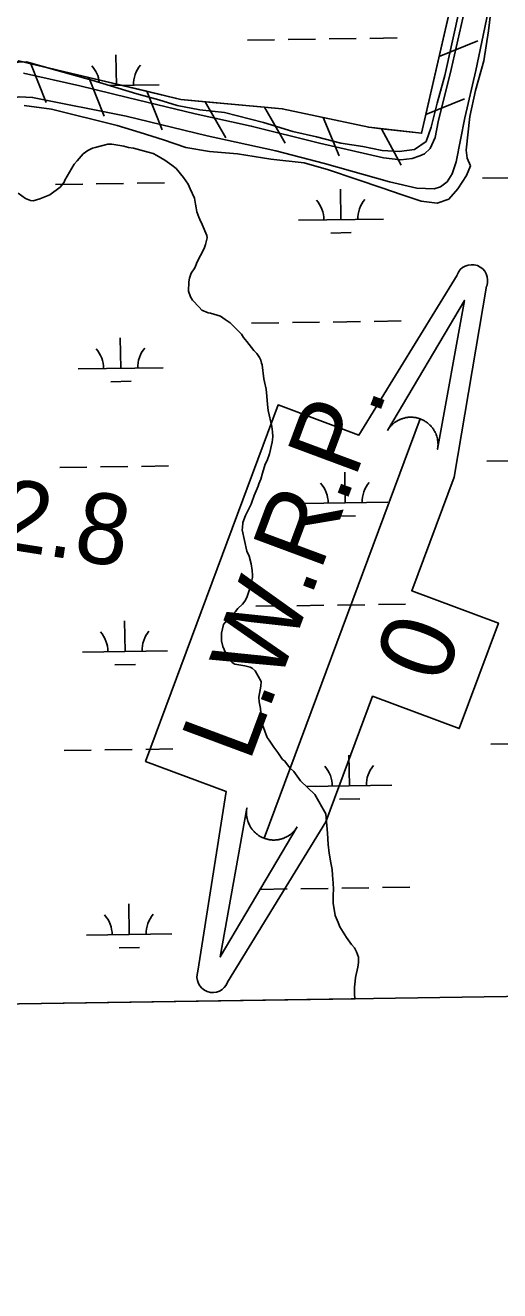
# Model space of a CAD drawing. Extents: x 3807117 to 3845308, y 337856 to 363736.
# Drawn here: x 3833871 to 3834429, y 343281 to 344768 of the extents above; entities that cross this region are included whole.
import ezdxf

# ---------------------------------------------------------------- set-up
doc = ezdxf.new("R2010")
doc.units = 0
for name, color, linetype in [('V-GRID-FRAM', 7, 'Continuous'), ('V-LEVE-TOET', 7, 'Continuous'), ('V-RIVR-EDGE', 7, 'Continuous'), ('V-RIVR-RANG-IDEN', 7, 'Continuous'), ('V-RRAP-FSHR', 7, 'Continuous'), ('V-SITE-VEGE', 7, 'Continuous'), ('V-TOPO-WATR-IDEN', 7, 'Continuous'), ('V-WETL-SWMP', 7, 'Continuous')]:
    doc.layers.add(name, color=color, linetype=linetype)

msp = doc.modelspace()

# ---------------------------------------------------------------- linework, layer by layer
at = {"layer": 'V-GRID-FRAM'}
msp.add_lwpolyline([(3811100.6, 361461.9), (3842914.2, 361938.5), (3843194.5, 343758.3), (3811365, 343281.4), (3811100.6, 361461.9)], dxfattribs=at)
at = {"layer": 'V-LEVE-TOET'}
for points in [[(3834420.2, 344809.1), (3834400.7, 344715.2), (3834387.8, 344659.5), (3834377.7, 344607.9), (3834373, 344593.7), (3834366.9, 344584.3), (3834359.3, 344578.4), (3834351.6, 344576.4), (3834331.4, 344577.1), (3834299.1, 344584.5), (3834222.9, 344605.8), (3834165.5, 344620.9), (3834084.7, 344638.6), (3833989.5, 344661.7), (3833879.6, 344683.7), (3833863.7, 344684.5), (3833851.9, 344682.1), (3833845.7, 344680.3), (3833834.3, 344673.2), (3833816.6, 344660.1), (3833785.8, 344626), (3833737, 344568.4)], [(3833869, 344712), (3833935.2, 344697.4), (3833991.3, 344683.7), (3834070.7, 344664.4), (3834136.7, 344649.9), (3834217.1, 344629.8), (3834292.2, 344612.8), (3834312.7, 344610.1), (3834325.8, 344611.9), (3834334.7, 344614.9), (3834340.3, 344617.4), (3834347, 344623.5), (3834352.7, 344636.7), (3834356.4, 344654.8), (3834371.8, 344716.3), (3834391.2, 344803)]]:
    msp.add_lwpolyline(points, dxfattribs=at)
at = {"layer": 'V-RIVR-EDGE'}
msp.add_spline([(3833993.6, 346073.1), (3834014.8, 346049.1), (3834027.9, 346045), (3834044.2, 346044.5), (3834056.4, 346046.8), (3834063.2, 346046.7), (3834065.5, 346045.4), (3834066.8, 346025), (3834070.8, 346004.7), (3834083.3, 345964.4), (3834083.8, 345960.8), (3834080.2, 345959.9), (3834071.6, 345964), (3834066.6, 345963.1), (3834057.1, 345958.1), (3834056.2, 345945.9), (3834053.9, 345939.6), (3834045.3, 345936), (3834032.2, 345933.8), (3834020.9, 345934.3), (3834010.5, 345930.7), (3833991.4, 345919.4), (3833968.3, 345903.6), (3833937.1, 345880.2), (3833918, 345855.8), (3833899.9, 345825.6), (3833887.6, 345788.5), (3833879.4, 345756.5), (3833874.3, 345710.4), (3833869.2, 345675.1), (3833852.3, 345618.6), (3833845.5, 345588.3), (3833842.7, 345557.2), (3833837.6, 345515.1), (3833834.3, 345463.1), (3833833.3, 345422.9), (3833835.5, 345389.9), (3833826.7, 345327.5), (3833812.6, 345266), (3833811.6, 345236.2), (3833805.6, 345198.2), (3833800.1, 345162.1), (3833798.7, 345131.8), (3833801.8, 345114.6), (3833810.8, 345092.4), (3833826.6, 345068.4), (3833838.7, 345048.9), (3833853.2, 345041.2), (3833864.5, 345032.1), (3833872.1, 345019.5), (3833872.1, 345008.2), (3833866.1, 344947.6), (3833859.1, 344872.5), (3833858.2, 344868), (3833853.6, 344868), (3833833.3, 344878), (3833815.7, 344894.8), (3833804.9, 344906.1), (3833797.7, 344908.9), (3833783.2, 344908.5), (3833736.6, 344893.2), (3833706.2, 344865.7), (3833687.6, 344845.4), (3833676.3, 344827.3), (3833665.4, 344800.7), (3833650.8, 344767.7), (3833632.6, 344715.8), (3833615.3, 344663.8), (3833598.9, 344623.1), (3833579.4, 344582.5), (3833566.6, 344539.6), (3833556.6, 344505.7), (3833525.6, 344416.7), (3833510.6, 344373.8), (3833496, 344333.1), (3833486.9, 344308.7), (3833473.3, 344271.2), (3833455.1, 344226.1), (3833441.8, 344180.9), (3833432.7, 344150.1), (3833396.3, 344055.7), (3833377.2, 344001.1), (3833358.1, 343958.6), (3833345.4, 343934.2), (3833328.1, 343879.6), (3833313, 343821.7), (3833296.6, 343775.6), (3833286.1, 343739.5), (3833276, 343687.1), (3833267.4, 343655), (3833255.1, 343614.3), (3833253.2, 343609.3)], degree=3, dxfattribs=at)
at = {"layer": 'V-RRAP-FSHR'}
for p, q in [((3834357.6, 344731.7), (3834402.9, 344750.1)), ((3833877.6, 344723.2), (3833895.6, 344677.8)), ((3833945.7, 344707), (3833963.7, 344661.6)), ((3834013.8, 344690.8), (3834031.8, 344645.4)), ((3834342, 344663.5), (3834387.2, 344681.9)), ((3834082.6, 344678.6), (3834106.8, 344636.3)), ((3834152.3, 344672.3), (3834176.5, 344629.9)), ((3834221.1, 344660.1), (3834240.1, 344615.1)), ((3834289.8, 344646.9), (3834313.1, 344603.9))]:
    msp.add_line(p, q, dxfattribs=at)
for points in [[(3833587.4, 344306.4), (3833655.4, 344519.2), (3833727.5, 344609.7), (3833863.6, 344726.6), (3834054, 344681.3), (3834173.1, 344670.3), (3834274.8, 344648.6), (3834336.9, 344641.5), (3834420.3, 345004.8), (3834419, 345047), (3834294.5, 345071.8), (3834199.7, 345056.1), (3834130, 345085.7), (3834142, 345154.9), (3834217.5, 345146.3), (3834217.8, 345245.8), (3834184, 345393.3)], [(3834357.6, 344731.7), (3834373.3, 344800)], [(3833821.4, 344690.4), (3833863.6, 344726.6), (3833877.6, 344723.2)], [(3834342, 344663.5), (3834357.6, 344731.7)], [(3833877.6, 344723.2), (3833945.7, 344707)], [(3833945.7, 344707), (3834013.8, 344690.8)], [(3834013.8, 344690.8), (3834054, 344681.3), (3834082.6, 344678.6)], [(3834082.6, 344678.6), (3834152.3, 344672.3)], [(3834152.3, 344672.3), (3834173.1, 344670.3), (3834221.1, 344660.1)], [(3834221.1, 344660.1), (3834274.8, 344648.6), (3834289.8, 344646.9)], [(3834289.8, 344646.9), (3834336.9, 344641.5), (3834342, 344663.5)]]:
    msp.add_lwpolyline(points, dxfattribs=at)
at = {"layer": 'V-SITE-VEGE'}
for p, q in [((3833939.1, 344617.4), (3833944.6, 344621.1)), ((3833944.6, 344621.1), (3833950.1, 344623.9)), ((3833950.1, 344623.9), (3833953.4, 344624.8)), ((3833953.4, 344624.8), (3833968.1, 344628.6)), ((3833968.1, 344628.6), (3833972.7, 344628.6)), ((3833972.7, 344628.6), (3833987, 344626.3)), ((3833987, 344626.3), (3833992.5, 344624.9)), ((3833992.5, 344624.9), (3833998.1, 344624)), ((3833998.1, 344624), (3834015.6, 344619.4)), ((3833928.5, 344605), (3833932.2, 344609.1)), ((3833932.2, 344609.1), (3833939.1, 344617.4)), ((3834015.6, 344619.4), (3834021.6, 344617.6)), ((3834021.6, 344617.6), (3834025.7, 344615.3)), ((3834025.7, 344615.3), (3834035, 344609.8)), ((3834035, 344609.8), (3834043.3, 344604.2)), ((3833917.5, 344586.5), (3833928.5, 344605)), ((3834043.3, 344604.2), (3834048.3, 344600.1)), ((3834048.3, 344600.1), (3834057.1, 344589.5)), ((3833900, 344569), (3833912, 344578.2)), ((3833912, 344578.2), (3833916.6, 344584.2)), ((3833916.6, 344584.2), (3833917.5, 344586.5)), ((3834057.1, 344589.5), (3834062.7, 344581.7)), ((3834062.7, 344581.7), (3834065, 344576.2)), ((3834065, 344576.2), (3834070.1, 344565.1)), ((3833862.6, 344571.2), (3833871.4, 344564.8)), ((3833871.4, 344564.8), (3833877.4, 344562.5)), ((3833877.4, 344562.5), (3833880.2, 344562)), ((3833880.2, 344562), (3833888, 344564.4)), ((3833888, 344564.4), (3833900, 344569)), ((3834070.1, 344565.1), (3834071, 344558.2)), ((3834071, 344558.2), (3834071.9, 344554)), ((3834071.9, 344554), (3834072.9, 344549)), ((3834072.9, 344549), (3834075.2, 344543)), ((3834075.2, 344543), (3834076.1, 344540.2)), ((3834076.1, 344540.2), (3834078.9, 344534.2)), ((3834078.9, 344534.2), (3834084.4, 344521.3)), ((3834084.9, 344518.6), (3834083.1, 344510.7)), ((3834084.4, 344521.3), (3834084.9, 344518.6)), ((3834081.2, 344506.1), (3834072.9, 344489.5)), ((3834083.1, 344510.7), (3834081.2, 344506.1)), ((3834072, 344487.2), (3834070.2, 344483.5)), ((3834072.9, 344489.5), (3834072, 344487.2)), ((3834066.1, 344477.1), (3834064.2, 344471.1)), ((3834070.2, 344483.5), (3834066.1, 344477.1)), ((3834063.3, 344466.9), (3834062.9, 344455.9)), ((3834064.2, 344471.1), (3834063.3, 344466.9)), ((3834062.9, 344455.9), (3834065.2, 344449.4)), ((3834065.2, 344449.4), (3834067.5, 344445.3)), ((3834067.5, 344445.3), (3834075.3, 344437)), ((3834075.3, 344437), (3834078.6, 344433.8)), ((3834078.6, 344433.8), (3834085.9, 344430.5)), ((3834085.9, 344430.5), (3834088.7, 344430.1)), ((3834088.7, 344430.1), (3834100.7, 344426.4)), ((3834100.7, 344426.4), (3834106.2, 344422.7)), ((3834106.2, 344422.7), (3834111.8, 344418.6)), ((3834111.8, 344418.6), (3834125.2, 344405.3)), ((3834125.2, 344405.3), (3834126.5, 344403.4)), ((3834126.5, 344403.4), (3834127.5, 344401.6)), ((3834127.5, 344401.6), (3834131.6, 344397)), ((3834131.6, 344397), (3834139.9, 344386.4)), ((3834139.9, 344386.4), (3834143.2, 344382.7)), ((3834143.2, 344382.7), (3834146.4, 344378.1)), ((3834146.4, 344378.1), (3834147.8, 344374.9)), ((3834147.8, 344374.9), (3834148.7, 344371.2)), ((3834148.7, 344371.2), (3834149.6, 344369.3)), ((3834149.6, 344369.3), (3834151.5, 344352.8)), ((3834151.5, 344352.8), (3834152.4, 344349.5)), ((3834152.4, 344349.5), (3834154.3, 344340.8)), ((3834154.3, 344340.8), (3834155.2, 344332.5)), ((3834155.2, 344332.5), (3834155.7, 344322.8)), ((3834155.7, 344322.8), (3834156.6, 344315.9)), ((3834156.6, 344315.9), (3834160.8, 344297)), ((3834160.8, 344297), (3834161.7, 344290.5)), ((3834161.3, 344278.6), (3834158.1, 344264.7)), ((3834162.2, 344284.6), (3834161.3, 344278.6)), ((3834161.7, 344290.5), (3834162.2, 344284.6)), ((3834158.1, 344264.7), (3834155.3, 344256.9)), ((3834153, 344252.7), (3834149.8, 344242.1)), ((3834155.3, 344256.9), (3834153, 344252.7)), ((3834148, 344235.2), (3834145.7, 344229.7)), ((3834149.8, 344242.1), (3834148, 344235.2)), ((3834144.8, 344226.9), (3834140.2, 344215.8)), ((3834145.7, 344229.7), (3834144.8, 344226.9)), ((3834136.5, 344205.7), (3834130.1, 344192.3)), ((3834137.4, 344208), (3834136.5, 344205.7)), ((3834140.2, 344215.8), (3834137.4, 344208)), ((3834130.1, 344192.3), (3834126.9, 344184)), ((3834126.4, 344178), (3834126, 344175.3)), ((3834126, 344175.3), (3834131.5, 344150.4)), ((3834126.9, 344184), (3834126.4, 344178)), ((3834131.5, 344150.4), (3834134.3, 344144.4)), ((3834134.3, 344144.4), (3834136.6, 344135.6)), ((3834136.6, 344135.6), (3834137.6, 344127.8)), ((3834138, 344119.5), (3834134.8, 344105.2)), ((3834137.6, 344127.8), (3834138, 344122.3)), ((3834138, 344122.3), (3834138, 344119.5)), ((3834133, 344100.6), (3834131.6, 344096)), ((3834134.8, 344105.2), (3834133, 344100.6)), ((3834126.6, 344088.2), (3834121, 344083.1)), ((3834129.3, 344091.8), (3834126.6, 344088.2)), ((3834131.6, 344096), (3834129.3, 344091.8)), ((3834110.9, 344072), (3834105.4, 344066)), ((3834118.3, 344079.4), (3834110.9, 344072)), ((3834121, 344083.1), (3834118.3, 344079.4)), ((3834104, 344064.1), (3834101.7, 344054)), ((3834105.4, 344066), (3834104, 344064.1)), ((3834101.7, 344054), (3834101.7, 344045.2)), ((3834101.7, 344045.2), (3834103.1, 344038.3)), ((3834103.1, 344038.3), (3834109.6, 344024.1)), ((3834109.6, 344024.1), (3834114.2, 344019.5)), ((3834114.2, 344019.5), (3834117.5, 344017.6)), ((3834117.5, 344017.6), (3834129, 344015.8)), ((3834129, 344015.8), (3834135.4, 344014)), ((3834135.4, 344014), (3834137.7, 344013)), ((3834137.7, 344013), (3834141.4, 344009.8)), ((3834141.4, 344009.8), (3834148.4, 343997.4)), ((3834148.4, 343997.4), (3834147.9, 343991.9)), ((3834147.9, 343991.9), (3834145.6, 343978.9)), ((3834145.6, 343978.9), (3834146.1, 343973.4)), ((3834146.1, 343973.4), (3834147.5, 343965.6)), ((3834147.5, 343965.6), (3834148.9, 343949.5)), ((3834148.9, 343949.5), (3834149.8, 343946.2)), ((3834149.8, 343946.2), (3834155.4, 343931.5)), ((3834155.4, 343931.5), (3834157.7, 343928.3)), ((3834157.7, 343928.3), (3834163.2, 343920)), ((3834163.2, 343920), (3834167.9, 343914)), ((3834167.9, 343914), (3834173.4, 343905.7)), ((3834173.4, 343905.7), (3834175.7, 343903.9)), ((3834175.7, 343903.9), (3834180.8, 343897.4)), ((3834180.8, 343897.4), (3834182.6, 343895.6)), ((3834182.6, 343895.6), (3834186.8, 343891.4)), ((3834186.8, 343891.4), (3834194.6, 343880.4)), ((3834194.6, 343880.4), (3834211.3, 343864.3)), ((3834211.3, 343864.3), (3834224.2, 343841.7)), ((3834224.2, 343841.7), (3834226.5, 343819.1)), ((3834226.5, 343819.1), (3834227, 343805.8)), ((3834227, 343805.8), (3834228.4, 343795.6)), ((3834228.4, 343795.6), (3834230.3, 343784.1)), ((3834230.3, 343784.1), (3834231.7, 343776.3)), ((3834231.7, 343776.3), (3834232.1, 343769.8)), ((3834232.1, 343769.8), (3834233.1, 343760.1)), ((3834233.1, 343760.1), (3834233.5, 343753.2)), ((3834233.5, 343753.2), (3834233.1, 343746.3)), ((3834233.1, 343746.3), (3834233.1, 343736.6)), ((3834233.1, 343736.6), (3834235.4, 343722.4)), ((3834235.4, 343722.4), (3834238.7, 343714.1)), ((3834238.7, 343714.1), (3834241, 343709)), ((3834241, 343709), (3834248.8, 343696.6)), ((3834248.8, 343696.6), (3834254.4, 343688.3)), ((3834254.4, 343688.3), (3834258.1, 343684.1)), ((3834258.1, 343684.1), (3834260.4, 343679.5)), ((3834260.4, 343679.5), (3834262.7, 343673.5)), ((3834262.7, 343673.5), (3834262.7, 343667.1)), ((3834261.8, 343661.6), (3834259.1, 343649.6)), ((3834262.7, 343667.1), (3834261.8, 343661.6)), ((3834258.6, 343641.3), (3834258.1, 343638.5)), ((3834259.1, 343649.6), (3834258.6, 343641.3)), ((3834258.8, 343624.4), (3833426.5, 343611.9)), ((3834258.1, 343638.5), (3834258.2, 343628.4)), ((3834258.2, 343628.4), (3834258.8, 343624.4))]:
    msp.add_line(p, q, dxfattribs=at)
at = {"layer": 'V-TOPO-WATR-IDEN'}
msp.add_line((3834152, 343813), (3834335.4, 344305.8), dxfattribs=at)
for points in [[(3834074.1, 343656.8), (3834107.4, 343868), (3834012.4, 343903.3), (3834168.3, 344322.2), (3834263.3, 344286.9), (3834378.6, 344474.9)], [(3834413.4, 344462), (3834375.1, 344237.3), (3834325.4, 344103.9), (3834427.3, 344066), (3834381.2, 343941.9), (3834279.3, 343979.9), (3834224.4, 343832.4), (3834108.9, 343643.8)]]:
    msp.add_lwpolyline(points, dxfattribs=at)
for points in [[(3834296.8, 344292.2), (3834387.3, 344445.1), (3834355.8, 344270.2), (3834356.2, 344273.4), (3834356.3, 344276.5), (3834356.2, 344277.7), (3834356.2, 344278.8), (3834356, 344280.1), (3834355.8, 344281.4), (3834355.6, 344282.5), (3834355.2, 344283.9), (3834354.8, 344285.5), (3834354.5, 344286.4), (3834354.1, 344287.5), (3834353.5, 344288.9), (3834353, 344290), (3834352.4, 344291.1), (3834351.9, 344291.9), (3834351.5, 344292.7), (3834350.8, 344293.7), (3834350.2, 344294.5), (3834349.6, 344295.4), (3834349.1, 344296), (3834348.2, 344297), (3834347.4, 344297.9), (3834346.7, 344298.6), (3834345.9, 344299.4), (3834345.1, 344300.1), (3834344.4, 344300.7), (3834343.9, 344301.1), (3834343.1, 344301.7), (3834342.2, 344302.3), (3834341.3, 344302.9), (3834340.4, 344303.4), (3834339.6, 344303.9), (3834338.6, 344304.4), (3834337.9, 344304.8), (3834336.7, 344305.3), (3834335.4, 344305.8), (3834335, 344305.9), (3834334.4, 344306.2), (3834333.7, 344306.4), (3834333, 344306.6), (3834332.3, 344306.8), (3834331.6, 344307), (3834330.8, 344307.1), (3834330.2, 344307.3), (3834329.4, 344307.4), (3834328.6, 344307.5), (3834328, 344307.6), (3834326.6, 344307.7), (3834325.9, 344307.8), (3834325.3, 344307.8), (3834324.5, 344307.8), (3834323.7, 344307.8), (3834322.9, 344307.8), (3834322, 344307.7), (3834321.1, 344307.7), (3834320.4, 344307.6), (3834319.8, 344307.5), (3834319, 344307.4), (3834318.3, 344307.3), (3834317.5, 344307.1), (3834316.7, 344306.9), (3834315.9, 344306.7), (3834314.8, 344306.4), (3834314.1, 344306.1), (3834313.3, 344305.9), (3834312.5, 344305.6), (3834311.9, 344305.3), (3834311.2, 344305), (3834310.2, 344304.5), (3834310.1, 344304.5), (3834309.6, 344304.2), (3834309.1, 344304), (3834308.5, 344303.7), (3834307.7, 344303.2), (3834307.1, 344302.8), (3834306.6, 344302.5), (3834305.9, 344302), (3834305.2, 344301.5), (3834304.8, 344301.2), (3834304.2, 344300.7), (3834303.4, 344300.1), (3834303, 344299.7), (3834302.6, 344299.4), (3834302.3, 344299.1), (3834301.9, 344298.7), (3834301.4, 344298.2), (3834300.9, 344297.7), (3834300.5, 344297.2), (3834300, 344296.7), (3834299.5, 344296.1), (3834299.1, 344295.6), (3834298.6, 344295), (3834298.1, 344294.2), (3834297.7, 344293.6), (3834297.4, 344293.1), (3834297.1, 344292.7), (3834296.9, 344292.4)], [(3834190.7, 343826.6), (3834100.2, 343673.6), (3834131.7, 343848.6), (3834131.3, 343845.4), (3834131.2, 343842.3), (3834131.2, 343841.1), (3834131.3, 343840), (3834131.5, 343838.7), (3834131.7, 343837.4), (3834131.9, 343836.3), (3834132.2, 343834.8), (3834132.7, 343833.3), (3834133, 343832.4), (3834133.4, 343831.3), (3834134, 343829.9), (3834134.5, 343828.8), (3834135.1, 343827.6), (3834135.5, 343826.9), (3834136, 343826.1), (3834136.6, 343825.1), (3834137.2, 343824.3), (3834137.9, 343823.4), (3834138.4, 343822.7), (3834139.2, 343821.8), (3834140, 343820.9), (3834140.7, 343820.2), (3834141.6, 343819.4), (3834142.3, 343818.7), (3834143, 343818.1), (3834143.6, 343817.7), (3834144.4, 343817.1), (3834145.3, 343816.4), (3834146.1, 343815.9), (3834147, 343815.3), (3834147.9, 343814.9), (3834148.8, 343814.4), (3834149.6, 343814), (3834150.7, 343813.5), (3834152, 343813), (3834152.4, 343812.8), (3834153, 343812.6), (3834153.8, 343812.4), (3834154.5, 343812.2), (3834155.2, 343812), (3834155.9, 343811.8), (3834156.7, 343811.6), (3834157.3, 343811.5), (3834158.1, 343811.4), (3834158.9, 343811.3), (3834159.4, 343811.2), (3834160.8, 343811.1), (3834161.6, 343811), (3834162.1, 343811), (3834163, 343811), (3834163.7, 343811), (3834164.5, 343811), (3834165.5, 343811.1), (3834166.4, 343811.1), (3834167, 343811.2), (3834167.6, 343811.3), (3834168.4, 343811.4), (3834169.1, 343811.5), (3834169.9, 343811.7), (3834170.8, 343811.9), (3834171.6, 343812.1), (3834172.6, 343812.4), (3834173.4, 343812.6), (3834174.2, 343812.9), (3834175, 343813.2), (3834175.6, 343813.5), (3834176.3, 343813.8), (3834177.3, 343814.2), (3834177.3, 343814.3), (3834177.9, 343814.6), (3834178.3, 343814.8), (3834179, 343815.1), (3834179.7, 343815.6), (3834180.4, 343816), (3834180.9, 343816.3), (3834181.6, 343816.8), (3834182.2, 343817.2), (3834182.7, 343817.6), (3834183.3, 343818), (3834184, 343818.7), (3834184.5, 343819.1), (3834184.9, 343819.4), (3834185.2, 343819.7), (3834185.6, 343820.1), (3834186, 343820.6), (3834186.5, 343821.1), (3834187, 343821.6), (3834187.4, 343822.1), (3834188, 343822.7), (3834188.3, 343823.1), (3834188.8, 343823.8), (3834189.4, 343824.6), (3834189.8, 343825.2), (3834190.1, 343825.6), (3834190.4, 343826.1), (3834190.6, 343826.4)]]:
    msp.add_lwpolyline(points, close=True, dxfattribs=at)
for centre, start, end in [((3834396, 344468.5), 339.5852, 159.5852), ((3834091.5, 343650.3), 159.5852, 339.5852)]:
    msp.add_arc(centre, 18.6, start, end, dxfattribs=at)
at = {"layer": 'V-WETL-SWMP'}
for p, q in [((3834364.4, 344709.2), (3834381.3, 344787.5)), ((3834420, 344798.3), (3834415.7, 344761.9)), ((3834415.7, 344761.9), (3834410.2, 344726.7)), ((3834132.1, 344750.9), (3834164.1, 344751.4)), ((3834180.1, 344751.6), (3834212.1, 344752.1)), ((3834228.1, 344752.3), (3834260.1, 344752.8)), ((3834276.1, 344753), (3834308.1, 344753.5)), ((3833853.7, 344724.7), (3833872.7, 344725.5)), ((3833872.7, 344725.5), (3833908.7, 344715.3)), ((3833978.3, 344697.8), (3833977.7, 344733.8)), ((3834410.2, 344726.7), (3834400.4, 344691.9)), ((3833908.7, 344715.3), (3833949.4, 344703.9)), ((3833949.4, 344703.9), (3834002.4, 344687.7)), ((3833969.6, 344697.7), (3834028.3, 344698.6)), ((3834355.3, 344676.8), (3834364.4, 344709.2)), ((3834002.4, 344687.7), (3834028.1, 344680.7)), ((3834028.1, 344680.7), (3834049.8, 344674)), ((3834400.4, 344691.9), (3834393.7, 344661.1)), ((3833902, 344669.8), (3833869.6, 344674.1)), ((3833979.1, 344650.6), (3833902, 344669.8)), ((3834049.8, 344674), (3834076.3, 344668.9)), ((3834076.3, 344668.9), (3834105.2, 344665.8)), ((3834105.2, 344665.8), (3834151, 344654)), ((3834348.3, 344648.7), (3834355.3, 344676.8)), ((3834006, 344642.3), (3833979.1, 344650.6)), ((3834151, 344654), (3834185.4, 344643.4)), ((3834393.7, 344661.1), (3834389.4, 344621.5)), ((3834033.7, 344633.6), (3834006, 344642.3)), ((3834185.4, 344643.4), (3834213.5, 344637.5)), ((3834213.5, 344637.5), (3834242, 344630)), ((3834342.4, 344631.7), (3834348.3, 344648.7)), ((3834059.8, 344624.6), (3834033.7, 344633.6)), ((3834087.5, 344619.9), (3834059.8, 344624.6)), ((3834242, 344630), (3834267.7, 344626.1)), ((3834267.7, 344626.1), (3834290.6, 344621.4)), ((3834290.6, 344621.4), (3834310.4, 344620.2)), ((3834310.4, 344620.2), (3834328.6, 344622.6)), ((3834328.6, 344622.6), (3834342.4, 344631.7)), ((3834389.4, 344621.5), (3834390.6, 344612.1)), ((3834120.7, 344617.2), (3834087.5, 344619.9)), ((3834159.8, 344610.9), (3834120.7, 344617.2)), ((3834198.9, 344606.6), (3834159.8, 344610.9)), ((3834227.4, 344598.4), (3834198.9, 344606.6)), ((3834390.6, 344612.1), (3834394.6, 344603.4)), ((3834260.2, 344587.4), (3834227.4, 344598.4)), ((3834389.9, 344591.9), (3834379.6, 344576.1)), ((3834394.6, 344603.4), (3834389.9, 344591.9)), ((3833906.6, 344581.3), (3833938.6, 344581.8)), ((3833954.6, 344582), (3833986.6, 344582.5)), ((3834002.6, 344582.8), (3834034.6, 344583.2)), ((3834242.1, 344539.9), (3834241.6, 344575.9)), ((3834291.5, 344577.1), (3834260.2, 344587.4)), ((3834312.8, 344569.6), (3834291.5, 344577.1)), ((3834379.6, 344576.1), (3834369, 344564.2)), ((3834408.5, 344588.8), (3834440.5, 344589.3)), ((3834336.6, 344561.8), (3834312.8, 344569.6)), ((3834355.1, 344559.4), (3834336.6, 344561.8)), ((3834369, 344564.2), (3834355.1, 344559.4)), ((3834192.1, 344539.2), (3834292.1, 344540.7)), ((3834230.4, 344524.3), (3834254.3, 344524.7)), ((3834137.1, 344418.3), (3834169.1, 344418.7)), ((3834185.1, 344419), (3834217.1, 344419.5)), ((3834233.1, 344419.7), (3834265.1, 344420.2)), ((3834281.1, 344420.4), (3834313.1, 344420.9)), ((3833983.3, 344365.2), (3833982.7, 344401.2)), ((3833933.3, 344364.5), (3834033.3, 344366)), ((3833971.5, 344349.6), (3833995.5, 344350)), ((3833911.6, 344248.7), (3833943.6, 344249.2)), ((3833959.6, 344249.4), (3833991.6, 344249.9)), ((3834007.6, 344250.1), (3834039.6, 344250.6)), ((3834413.5, 344256.2), (3834445.4, 344256.7)), ((3834247.1, 344207.3), (3834246.6, 344243.3)), ((3834197.1, 344206.5), (3834297.1, 344208)), ((3834235.3, 344191.7), (3834259.3, 344192)), ((3834142.1, 344085.6), (3834174.1, 344086.1)), ((3834190.1, 344086.3), (3834222.1, 344086.8)), ((3834238.1, 344087.1), (3834270.1, 344087.5)), ((3834286.1, 344087.8), (3834318, 344088.3)), ((3833988.3, 344032.6), (3833987.7, 344068.6)), ((3833938.3, 344031.8), (3834038.2, 344033.3)), ((3833976.5, 344017), (3834000.5, 344017.3)), ((3834418.4, 343923.6), (3834450.4, 343924)), ((3833916.6, 343916), (3833948.6, 343916.5)), ((3833964.6, 343916.8), (3833996.6, 343917.2)), ((3834012.6, 343917.5), (3834044.6, 343918)), ((3834252.1, 343874.6), (3834251.5, 343910.6)), ((3834202.1, 343873.9), (3834302.1, 343875.4)), ((3834240.3, 343859), (3834264.3, 343859.4)), ((3834147.1, 343753), (3834179, 343753.5)), ((3834195, 343753.7), (3834227, 343754.2)), ((3834243, 343754.4), (3834275, 343754.9)), ((3834291, 343755.1), (3834323, 343755.6)), ((3833993.2, 343699.9), (3833992.7, 343735.9)), ((3833943.2, 343699.2), (3834043.2, 343700.7)), ((3833981.5, 343684.3), (3834005.5, 343684.7)), ((3833414.8, 343611.8), (3835523.3, 343643.3))]:
    msp.add_line(p, q, dxfattribs=at)
for centre, start, end in [((3833923, 344697.5), 6.0823, 41.6302), ((3834033.5, 344699.1), 140.0865, 181.6302), ((3834186.9, 344539.6), 0.0865, 41.6302), ((3834297.3, 344541.2), 140.0865, 181.6302), ((3833928, 344364.8), 0.0865, 41.6302), ((3834038.5, 344366.5), 140.0865, 181.6302), ((3834191.9, 344206.9), 0.0865, 41.6302), ((3834302.3, 344208.6), 140.0865, 181.6302), ((3833933, 344032.2), 0.0865, 41.6302), ((3834043.5, 344033.9), 140.0865, 181.6302), ((3834196.8, 343874.3), 0.0865, 41.6302), ((3834307.3, 343875.9), 140.0865, 181.6302), ((3833938, 343699.6), 0.0865, 41.6302), ((3834048.5, 343701.2), 140.0865, 181.6302)]:
    msp.add_arc(centre, 35.2, start, end, dxfattribs=at)

# ---------------------------------------------------------------- texts
at = {"layer": 'V-RIVR-RANG-IDEN'}
msp.add_text('R-32.8', height=83, rotation=351.0894, dxfattribs=at).set_placement((3833657.7, 344182.7))
at = {"layer": 'V-TOPO-WATR-IDEN'}
for s, height, rotation, p in [('L.W.R.P.', 87.15, 69.5851, (3834134.4, 343901.1)), ('0', 87.2, 69.5852, (3834362.1, 343992.1))]:
    msp.add_text(s, height=height, rotation=rotation, dxfattribs=at).set_placement(p)

doc.saveas('drawing.dxf')
